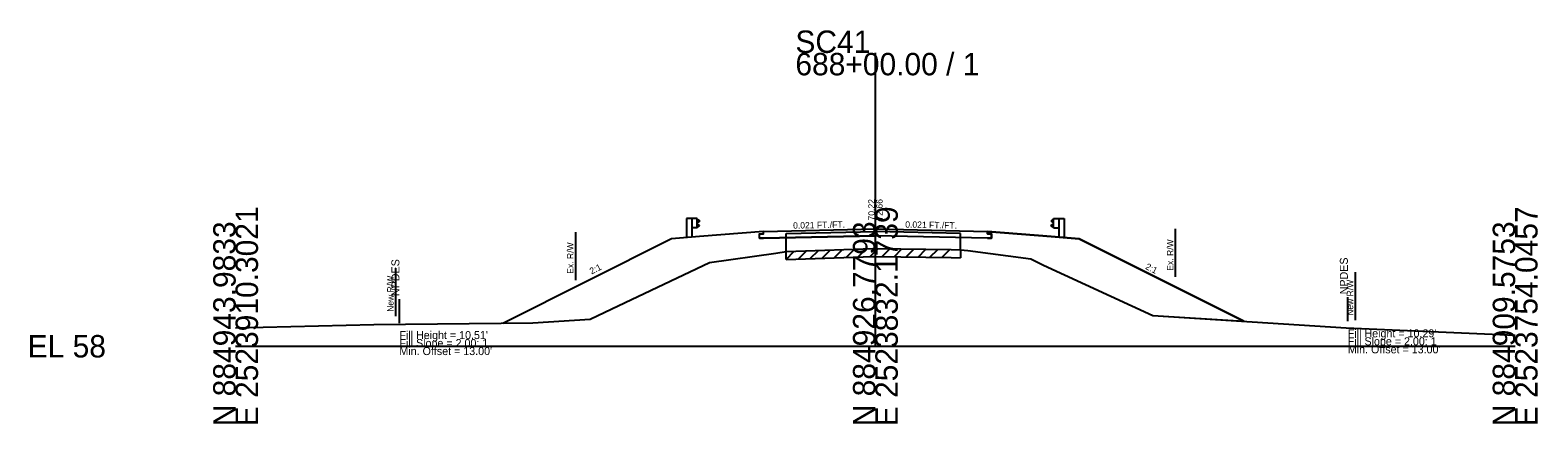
# Model space of a CAD drawing. Extents: x -26 to 183, y -10 to 24021.
# Drawn here: x -25.7 to 162.8, y 15990.3 to 16039.5 of the extents above; entities that cross this region are included whole.
import ezdxf

# ---------------------------------------------------------------- set-up
doc = ezdxf.new("R2010")
doc.units = 0
for name, color, linetype in [('RD_GPK_XS_Cell', 7, 'Continuous'), ('RD_XS_Base', 7, 'Continuous'), ('RD_XS_Buildup', 7, 'Continuous'), ('RD_XS_EarthShd', 7, 'Continuous'), ('RD_XS_EwShp', 7, 'Continuous'), ('RD_XS_ExGround', 7, 'Continuous'), ('RD_XS_ExPaveRet', 7, 'Continuous'), ('RD_XS_ExRW', 7, 'Continuous'), ('RD_XS_GR', 7, 'Continuous'), ('RD_XS_NewRW', 7, 'Continuous'), ('RD_XS_NPDES', 7, 'Continuous'), ('RD_XS_Pave', 7, 'Continuous'), ('RD_XS_TieSlope', 7, 'Continuous'), ('RD_XS_TX_Elev_EX', 7, 'Continuous'), ('RD_XS_TX_Elev_PR', 7, 'Continuous'), ('RD_XS_TX_Slope', 7, 'Continuous'), ('RD_XS_TX_Warning', 7, 'Continuous')]:
    doc.layers.add(name, color=color, linetype=linetype)

msp = doc.modelspace()

# ---------------------------------------------------------------- linework, layer by layer
at = {"layer": 'RD_GPK_XS_Cell'}
for p, q in [((80, 16000), (80, 16036.66)), ((0, 16000), (80, 16000)), ((80, 16000), (160, 16000))]:
    msp.add_line(p, q, dxfattribs=at)
at = {"layer": 'RD_XS_Base'}
for p in [(66.01, 16013.52), (94, 16013.52)]:
    msp.add_line(p, (80, 16013.81), dxfattribs=at)
at = {"layer": 'RD_XS_Buildup'}
for p, q in [((68.83, 16014.1), (80, 16014.34)), ((68.83, 16011.85), (68.83, 16014.1)), ((90.63, 16014.11), (80, 16014.34)), ((90.63, 16012.06), (90.63, 16014.11))]:
    msp.add_line(p, q, dxfattribs=at)
at = {"layer": 'RD_XS_EarthShd'}
for p, q in [((66, 16014.36), (58, 16013.7)), ((94, 16014.36), (102, 16013.7)), ((58, 16013.7), (54.5, 16013.41)), ((102, 16013.7), (105.5, 16013.41))]:
    msp.add_line(p, q, dxfattribs=at)
at = {"layer": 'RD_XS_EwShp'}
msp.add_lwpolyline([(67.57, 16011.64), (68.83, 16011.85), (70.07, 16011.89), (79.69, 16012.22), (80, 16012.22), (89.47, 16012.08), (90.63, 16012.06), (91.55, 16011.95), (99.43, 16010.91), (101.01, 16010.13), (114.71, 16003.83), (126.08, 16003.12), (105.5, 16013.41), (102, 16013.7), (94, 16014.36), (94, 16014.07), (94.5, 16014.06), (94.5, 16013.51), (94, 16013.52), (80, 16013.81), (66.01, 16013.52), (65.5, 16013.51), (65.5, 16014.06), (66, 16014.07), (66, 16014.36), (58, 16013.7), (54.5, 16013.41), (33.48, 16002.9), (37.15, 16002.93), (44.34, 16003.39), (47.05, 16004.69), (59.27, 16010.48)], close=True, dxfattribs=at)
msp.add_lwpolyline([(67.57, 16011.64), (68.83, 16011.85), (70.07, 16011.89), (79.69, 16012.22), (80, 16012.22), (89.47, 16012.08), (90.63, 16012.06), (91.55, 16011.95), (99.43, 16010.91), (101.01, 16010.13), (114.71, 16003.83), (126.08, 16003.12), (105.5, 16013.41), (102, 16013.7), (94, 16014.36), (94, 16014.07), (94.5, 16014.06), (94.5, 16013.51), (94, 16013.52), (80, 16013.81), (66.01, 16013.52), (65.5, 16013.51), (65.5, 16014.06), (66, 16014.07), (66, 16014.36), (58, 16013.7), (54.5, 16013.41), (33.48, 16002.9), (37.15, 16002.93), (44.34, 16003.39), (47.05, 16004.69), (59.27, 16010.48)], close=True, dxfattribs=at)
msp.add_lwpolyline([(67.57, 16011.64), (68.83, 16011.85), (70.07, 16011.89), (79.69, 16012.22), (80, 16012.22), (89.47, 16012.08), (90.63, 16012.06), (91.55, 16011.95), (99.43, 16010.91), (101.01, 16010.13), (114.71, 16003.83), (126.08, 16003.12), (105.5, 16013.41), (102, 16013.7), (94, 16014.36), (94, 16014.07), (94.5, 16014.06), (94.5, 16013.51), (94, 16013.52), (80, 16013.81), (66.01, 16013.52), (65.5, 16013.51), (65.5, 16014.06), (66, 16014.07), (66, 16014.36), (58, 16013.7), (54.5, 16013.41), (33.48, 16002.9), (37.15, 16002.93), (44.34, 16003.39), (47.05, 16004.69), (59.27, 16010.48)], close=True, dxfattribs=at)
msp.add_lwpolyline([(67.57, 16011.64), (68.83, 16011.85), (70.07, 16011.89), (79.69, 16012.22), (80, 16012.22), (89.47, 16012.08), (90.63, 16012.06), (91.55, 16011.95), (99.43, 16010.91), (101.01, 16010.13), (114.71, 16003.83), (126.08, 16003.12), (105.5, 16013.41), (102, 16013.7), (94, 16014.36), (94, 16014.07), (94.5, 16014.06), (94.5, 16013.51), (94, 16013.52), (80, 16013.81), (66.01, 16013.52), (65.5, 16013.51), (65.5, 16014.06), (66, 16014.07), (66, 16014.36), (58, 16013.7), (54.5, 16013.41), (33.48, 16002.9), (37.15, 16002.93), (44.34, 16003.39), (47.05, 16004.69), (59.27, 16010.48)], close=True, dxfattribs=at)
at = {"layer": 'RD_XS_ExGround'}
for p, q in [((70.07, 16011.89), (79.69, 16012.22)), ((79.69, 16012.22), (80, 16012.22)), ((80, 16012.22), (89.47, 16012.08)), ((89.47, 16012.08), (90.63, 16012.06)), ((47.05, 16004.69), (59.27, 16010.48)), ((59.27, 16010.48), (67.57, 16011.64)), ((67.57, 16011.64), (68.83, 16011.85)), ((68.83, 16011.85), (70.07, 16011.89)), ((90.63, 16012.06), (91.55, 16011.95)), ((91.55, 16011.95), (99.43, 16010.91)), ((99.43, 16010.91), (101.01, 16010.13)), ((101.01, 16010.13), (114.71, 16003.83)), ((44.34, 16003.39), (47.05, 16004.69)), ((0, 16002.3), (17.27, 16002.72)), ((17.27, 16002.72), (37.15, 16002.93)), ((37.15, 16002.93), (44.34, 16003.39)), ((114.71, 16003.83), (138.87, 16002.31)), ((138.87, 16002.31), (160, 16001.39))]:
    msp.add_line(p, q, dxfattribs=at)
at = {"layer": 'RD_XS_ExPaveRet'}
for p, q in [((74.83, 16011.05), (75.87, 16012.09)), ((76.33, 16011.1), (77.37, 16012.14)), ((77.83, 16011.16), (78.87, 16012.19)), ((79.33, 16011.21), (80.33, 16012.21)), ((80.83, 16011.2), (81.82, 16012.19)), ((82.33, 16011.18), (83.32, 16012.17)), ((83.83, 16011.16), (84.82, 16012.15)), ((85.33, 16011.14), (86.32, 16012.13)), ((86.83, 16011.12), (87.82, 16012.1)), ((88.33, 16011.1), (89.32, 16012.08)), ((68.83, 16010.85), (69.86, 16011.88)), ((68.83, 16010.85), (68.83, 16011.85)), ((68.83, 16010.85), (70.07, 16010.89)), ((70.07, 16010.89), (79.69, 16011.22)), ((70.33, 16010.9), (71.37, 16011.93)), ((71.83, 16010.95), (72.87, 16011.98)), ((73.33, 16011), (74.37, 16012.04)), ((79.69, 16011.22), (80, 16011.22)), ((80, 16011.22), (89.47, 16011.08)), ((89.47, 16011.08), (90.63, 16011.06)), ((90.63, 16012.06), (90.63, 16011.06))]:
    msp.add_line(p, q, dxfattribs=at)
at = {"layer": 'RD_XS_ExRW'}
for p, q in [((42.5, 16014.27), (42.5, 16008.27)), ((117.5, 16014.66), (117.5, 16008.66))]:
    msp.add_line(p, q, dxfattribs=at)
at = {"layer": 'RD_XS_GR'}
for p, q in [((56.4, 16015.95), (56.4, 16013.56)), ((57.06, 16015.95), (56.4, 16015.95)), ((57.06, 16015.95), (57.06, 16013.62)), ((57.73, 16015.95), (57.06, 16015.95)), ((57.73, 16014.78), (57.73, 16015.95)), ((57.73, 16015.87), (58, 16015.67)), ((102.27, 16015.87), (102, 16015.67)), ((102.27, 16014.78), (102.27, 16015.95)), ((102.27, 16015.95), (102.94, 16015.95)), ((102.94, 16015.95), (102.94, 16013.62)), ((102.94, 16015.95), (103.6, 16015.95)), ((103.6, 16015.95), (103.6, 16013.56)), ((57.73, 16014.78), (57.06, 16014.78)), ((58, 16015.62), (57.73, 16015.42)), ((58, 16015.1), (57.73, 16015.3)), ((57.73, 16014.85), (58, 16015.05)), ((58, 16015.67), (58, 16015.62)), ((58, 16015.05), (58, 16015.1)), ((102, 16015.67), (102, 16015.62)), ((102, 16015.62), (102.27, 16015.42)), ((102, 16015.1), (102.27, 16015.3)), ((102, 16015.05), (102, 16015.1)), ((102.27, 16014.85), (102, 16015.05)), ((102.27, 16014.78), (102.94, 16014.78))]:
    msp.add_line(p, q, dxfattribs=at)
at = {"layer": 'RD_XS_NewRW'}
for p, q in [((20, 16009.75), (20, 16003.75)), ((140, 16009.26), (140, 16003.26))]:
    msp.add_line(p, q, dxfattribs=at)
at = {"layer": 'RD_XS_NPDES'}
for p, q in [((20.48, 16002.9), (20.48, 16005.9)), ((139.08, 16003.12), (139.08, 16006.12))]:
    msp.add_line(p, q, dxfattribs=at)
at = {"layer": 'RD_XS_Pave'}
for p, q in [((65.5, 16014.06), (66, 16014.07)), ((65.5, 16013.51), (65.5, 16014.06)), ((66, 16014.36), (80, 16014.66)), ((66, 16014.07), (66, 16014.36)), ((80, 16014.66), (94, 16014.36)), ((94, 16014.07), (94, 16014.36)), ((94.5, 16014.06), (94, 16014.07)), ((94.5, 16013.51), (94.5, 16014.06)), ((65.5, 16013.51), (66.01, 16013.52)), ((94, 16013.52), (94.5, 16013.51))]:
    msp.add_line(p, q, dxfattribs=at)
at = {"layer": 'RD_XS_TieSlope'}
for p, q in [((54.5, 16013.41), (33.48, 16002.9)), ((105.5, 16013.41), (126.08, 16003.12))]:
    msp.add_line(p, q, dxfattribs=at)

# ---------------------------------------------------------------- texts
at = {"layer": 'RD_GPK_XS_Cell'}
for s, p in [('SC41', (70, 16036.66)), ('688+00.00 / 1', (70, 16033.86)), ('EL 58', (-26, 15998.6))]:
    msp.add_text(s, height=2.8, dxfattribs=at).set_placement(p)
for s, p in [('E 2523910.3021', (2.8, 15990)), ('E 2523832.1739', (82.8, 15990)), ('E 2523754.0457', (162.8, 15990)), ('N 884943.9833', (0, 15990)), ('N 884926.7793', (80, 15990)), ('N 884909.5753', (160, 15990))]:
    msp.add_text(s, height=2.8, rotation=90, dxfattribs=at).set_placement(p)
at = {"layer": 'RD_XS_ExRW'}
for p in [(42.25, 16009.06), (117.25, 16009.44)]:
    msp.add_text('Ex. R/W ', height=0.8, rotation=90, dxfattribs=at).set_placement(p)
at = {"layer": 'RD_XS_NewRW'}
for p in [(19.75, 16004.3), (139.75, 16003.8)]:
    msp.add_text('New R/W ', height=0.8, rotation=90, dxfattribs=at).set_placement(p)
at = {"layer": 'RD_XS_TX_Elev_EX'}
msp.add_text('70.22', height=0.8, rotation=90, dxfattribs=at).set_placement((79.9, 16015.72))
at = {"layer": 'RD_XS_TX_Elev_PR'}
msp.add_text('72.66', height=0.8, rotation=90, dxfattribs=at).set_placement((80.9, 16015.72))
at = {"layer": 'RD_XS_TX_Slope'}
for s, rotation, p in [('0.021 FT./FT.', 1.1916, (69.72, 16014.69)), ('0.021 FT./FT.', 358.8084, (83.73, 16014.83)), ('2:1', 26.5651, (44.51, 16008.97)), ('2:1', 333.4349, (113.69, 16009.7))]:
    msp.add_text(s, height=0.8, rotation=rotation, dxfattribs=at).set_placement(p)
at = {"layer": 'RD_XS_TX_Warning'}
for p in [(20.48, 16005.9), (139.08, 16006.12)]:
    msp.add_text(' NPDES', height=1, rotation=90, dxfattribs=at).set_placement(p)
for s, p in [("Fill Height = 10.51' ", (20.48, 16000.9)), ('Fill Slope = 2.00: 1', (20.48, 15999.9)), ("Fill Height = 10.29' ", (139.08, 16001.12)), ('Fill Slope = 2.00: 1', (139.08, 16000.12)), ("Min. Offset = 13.00' ", (20.48, 15998.9)), ("Min. Offset = 13.00' ", (139.08, 15999.12))]:
    msp.add_text(s, height=1, dxfattribs=at).set_placement(p)

doc.saveas('drawing.dxf')
